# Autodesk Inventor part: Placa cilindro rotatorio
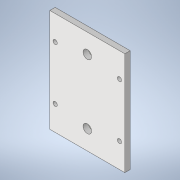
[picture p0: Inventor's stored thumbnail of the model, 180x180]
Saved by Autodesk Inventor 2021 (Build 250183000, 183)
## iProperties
Created: 2021-02
Part Number: Placa cilindro rotatorio
Material: Genérico
Document SubType Name: Modeling
Designer: ATOUZA
Density: 1 g/cm^3
Appearance: Valor por defecto
Author: ATOUZA
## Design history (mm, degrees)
node "Plano de trabajo1"
sketch "Boceto1"
  geometry: L1 (50, 9.5)-(50, 82.5) reference; L2 (0, 0)-(50, 0) reference; L3 (0, 9.5)-(0, 82.5) reference; L4 (0, 0)-(0, 9.45) reference; L5 (50, 0)-(50, 9.45) reference; L6 (0, 92)-(50, 92) reference; L7 (60, 94)-(-10, 94); L8 (-10, 94)-(-10, -2); L9 (-10, -2)-(60, -2); L10 (60, -2)-(60, 94); L11 (60, 94)-(-10, -2); L12 (-10, 94)-(60, -2); L13 (60, 46)-(-10, 46); L14 (25, -2)-(25, 46); C1 r 4 at (25, 16) reference; C2 r 4 at (25, 76) reference; C3 r 3.323 at (25, 16) reference; C4 r 3.323 at (25, 76) reference; C5 r 3 at (25, 46) reference; C6 r 4 at (25, 16); C7 r 4 at (25, 76); C8 r 2 at (-5, 21); C9 r 2 at (-5, 71); C10 r 2 at (55, 21); C11 r 2 at (55, 71)
  constraints: 16 end point, 6 centre point, 5 midpoint, 3 symmetric about line, 2 coincident, 2 concentric, 2 parallel, 2 perpendicular, 1 horizontal, 3 other
  dimensions: "d0" = 70 distance of L9.end L8.end; "d1" = 96 distance of L8.end L7.end; "d2" = 4 diameter of C8; "d3" = 5 distance from line of L8 C8.centre; "d6" = 23 distance from line of L9 C8.centre
extrude "Extrusión1" new body sketch "Boceto1" distance "d4" = 5; taper "d5" = 0 deg
fillet "Empalme1" dims "d7" = 4
node "Sólido1"
node "Referencia1"
node "Referencia2"
node "Referencia3"
node "Referencia4"
node "Referencia6"
node "Referencia7"
node "Referencia8"
node "Referencia9"
node "Referencia10"
node "Referencia11"
node "Referencia12"
